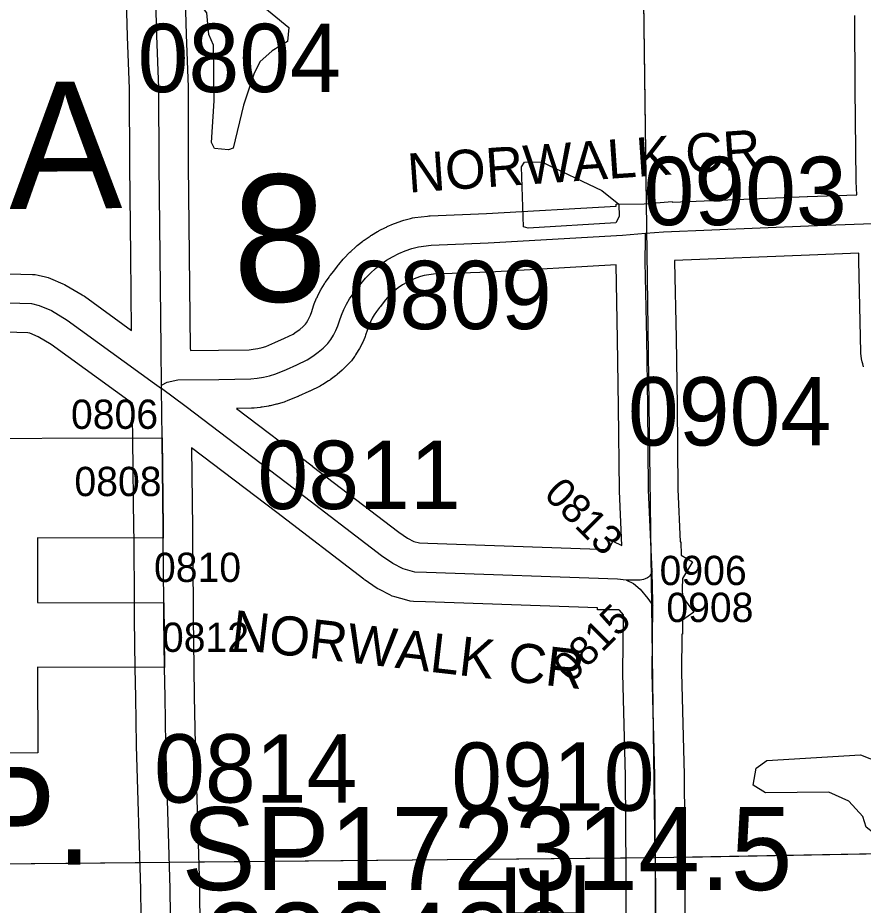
# Model space of a CAD drawing. Extents: x 23.6 to 68.7, y -63 to -29.
# Drawn here: x 46.003 to 46.869, y -47.606 to -46.697 of the extents above; entities that cross this region are included whole.
import ezdxf

# ---------------------------------------------------------------- set-up
doc = ezdxf.new("R2010")
doc.units = 0
for name, color, linetype in [('tdCoCorpBndry', 7, 'Continuous'), ('tdCoCorpPopTxt', 7, 'Continuous'), ('tdCoCorpTxt', 7, 'Continuous'), ('tdCoHydroRiver', 7, 'Continuous'), ('tdCoSecRdNmbr', 7, 'Continuous'), ('tdCoSecRdTxt', 7, 'Continuous'), ('tdCoSecRteBand', 7, 'Continuous'), ('tdCoSecRteCL', 7, 'Continuous'), ('tdCoSectLine', 7, 'Continuous'), ('tdCoSectLinePart', 7, 'Continuous'), ('tdCoSectNmbr', 7, 'Continuous'), ('tdCoStrucSecCoName', 7, 'Continuous'), ('tdCoStrucSecFHWANum', 7, 'Continuous'), ('tdCoSurfGravel', 7, 'Continuous')]:
    doc.layers.add(name, color=color, linetype=linetype)

msp = doc.modelspace()

# ---------------------------------------------------------------- linework, layer by layer
at = {"layer": 'tdCoCorpBndry'}
msp.add_lwpolyline([(45.9041, -47.12823), (46.15075, -47.12738), (46.15186, -47.22042), (46.15192, -47.23031), (46.02292, -47.22989), (46.02298, -47.29617), (46.15237, -47.2966), (46.15325, -47.36289), (46.02304, -47.36246), (46.02355, -47.45028), (45.90584, -47.45112)], dxfattribs=at)
at = {"layer": 'tdCoHydroRiver'}
for points in [[(46.21866, -46.83257), (46.20444, -46.83114), (46.20121, -46.82486), (46.2039, -46.78222), (46.20328, -46.72539), (46.19843, -46.71439), (46.19661, -46.69232), (46.1918, -46.68606), (46.1901, -46.67502), (46.18204, -46.65932), (46.18015, -46.63093), (46.22891, -46.61461), (46.23841, -46.61766), (46.2432, -46.62235), (46.25017, -46.68225), (46.28043, -46.70718), (46.27901, -46.7214), (46.26332, -46.73105), (46.25082, -46.74223), (46.24465, -46.75493), (46.23394, -46.78662), (46.22338, -46.83093), (46.21866, -46.83257)], [(46.52578, -46.91286), (46.52102, -46.91134), (46.51877, -46.8498), (46.52188, -46.84502), (46.53924, -46.84483), (46.60112, -46.87415), (46.61863, -46.88816), (46.61878, -46.90079), (46.61569, -46.90714), (46.52578, -46.91286)], [(46.89719, -47.53232), (46.87982, -47.53251), (46.87186, -47.52629), (46.86859, -47.51527), (46.85421, -47.49964), (46.83359, -47.49039), (46.76887, -47.49111), (46.75616, -47.48335), (46.75913, -47.46596), (46.77009, -47.45795), (46.86632, -47.45215), (46.88534, -47.45983), (46.89176, -47.46924), (46.90022, -47.52124), (46.89719, -47.53232)]]:
    msp.add_lwpolyline(points, dxfattribs=at)
at = {"layer": 'tdCoSecRteBand'}
for points in [[(45.95845, -46.95837), (46.01788, -46.96009), (46.02078, -46.96018), (46.02361, -46.96082), (46.03126, -46.96254), (46.03398, -46.96316), (46.03653, -46.96426), (46.04911, -46.96969), (46.05086, -46.97044), (46.05249, -46.9714), (46.06877, -46.98102), (46.06997, -46.98173), (46.07111, -46.98256), (46.1194, -47.01755), (46.11857, -46.94106), (46.11755, -46.84858), (46.11754, -46.84846), (46.11754, -46.84833), (46.11734, -46.76995), (46.1153, -46.71643), (46.1153, -46.71626), (46.11529, -46.7161), (46.11365, -46.65527)], [(46.17364, -46.65396), (46.17527, -46.71431), (46.17732, -46.7682), (46.17734, -46.76873), (46.17734, -46.76926), (46.17754, -46.84805), (46.17857, -46.9404), (46.17857, -46.9404), (46.17857, -46.9404), (46.1796, -47.03552), (46.17963, -47.03802)], [(46.17963, -47.03802), (46.20849, -47.03768), (46.23999, -47.03721), (46.24415, -47.03677), (46.24867, -47.03601), (46.25312, -47.03497), (46.25693, -47.03382), (46.26605, -47.03), (46.27609, -47.02546), (46.28486, -47.02121), (46.28818, -47.0191), (46.29183, -47.01641), (46.29528, -47.01346), (46.29756, -47.0112), (46.29856, -47.00984), (46.30012, -47.00733), (46.30148, -47.00471), (46.30265, -47.00199), (46.30393, -46.99825), (46.30587, -46.99242), (46.30621, -46.9914), (46.30662, -46.9904), (46.30902, -46.98461), (46.30944, -46.98361), (46.30992, -46.98265), (46.31273, -46.97705), (46.31322, -46.97608), (46.31377, -46.97516), (46.31697, -46.96977), (46.31753, -46.96885), (46.31814, -46.96796), (46.32173, -46.96282), (46.32235, -46.96194), (46.32303, -46.9611), (46.32654, -46.95676), (46.33036, -46.95159), (46.33095, -46.95078), (46.33159, -46.95003), (46.33618, -46.9446), (46.33683, -46.94384), (46.33752, -46.94312), (46.34246, -46.93801), (46.34315, -46.9373), (46.34389, -46.93663), (46.34915, -46.93186), (46.34989, -46.93119), (46.35067, -46.93057), (46.35624, -46.92616), (46.35702, -46.92554), (46.35784, -46.92498), (46.36369, -46.92094), (46.36451, -46.92038), (46.36537, -46.91987), (46.37147, -46.91623), (46.37233, -46.91572), (46.37321, -46.91527), (46.37955, -46.91205), (46.38044, -46.9116), (46.38135, -46.91121), (46.38788, -46.90841), (46.3888, -46.90802), (46.38974, -46.90769), (46.39644, -46.90533), (46.39738, -46.905), (46.39834, -46.90473), (46.40518, -46.90282), (46.40732, -46.90222), (46.40952, -46.90195), (46.42268, -46.9003), (46.42394, -46.90015), (46.42521, -46.9001), (46.48315, -46.8978), (46.61579, -46.89021), (46.61577, -46.88814), (46.64464, -46.88795), (46.67341, -46.88559), (46.67345, -46.88603), (46.81168, -46.88037), (46.81173, -46.88037), (46.81178, -46.88036), (46.8623, -46.87847), (46.86184, -46.86501), (46.86183, -46.86465), (46.86183, -46.86429), (46.86087, -46.76986), (46.86087, -46.76981), (46.86087, -46.76976), (46.86038, -46.69495)], [(46.86935, -47.05485), (46.86851, -47.05183), (46.86788, -47.04959), (46.86704, -47.04657), (46.86684, -47.04345), (46.86668, -47.04112), (46.86664, -47.04047), (46.86663, -47.03982), (46.86463, -46.94636), (46.86436, -46.93843), (46.81409, -46.94032), (46.6757, -46.94599), (46.67568, -46.94708), (46.67731, -47.02514), (46.67732, -47.02524), (46.67732, -47.02534), (46.6783, -47.09488), (46.6783, -47.09495), (46.67831, -47.09502), (46.67912, -47.18), (46.68149, -47.23415), (46.68224, -47.23414), (46.68249, -47.24759), (46.694, -47.25456), (46.68369, -47.27158), (46.68359, -47.28221), (46.68394, -47.29023), (46.69528, -47.30613), (46.68372, -47.31436), (46.68398, -47.32855), (46.68316, -47.32856), (46.68279, -47.36783), (46.68541, -47.4727), (46.68541, -47.47295), (46.68541, -47.47319), (46.68624, -47.57085), (46.68624, -47.57092), (46.68624, -47.571), (46.68656, -47.66733)], [(46.60829, -47.24188), (46.6124, -47.23337), (46.62159, -47.23781), (46.61916, -47.18211), (46.61914, -47.1816), (46.61913, -47.18109), (46.61831, -47.09567), (46.61732, -47.02629), (46.61574, -46.95031), (46.48631, -46.95772), (46.48605, -46.95774), (46.48578, -46.95775), (46.42885, -46.96), (46.41917, -46.96121), (46.41542, -46.96226), (46.41059, -46.96395), (46.40588, -46.96597), (46.40132, -46.96829), (46.39693, -46.97091), (46.39271, -46.97381), (46.3887, -46.97699), (46.38491, -46.98043), (46.38135, -46.98411), (46.37804, -46.98802), (46.37441, -46.99293), (46.37401, -46.99348), (46.37358, -46.99401), (46.37032, -46.99804), (46.36797, -47.0014), (46.36587, -47.00493), (46.36403, -47.00859), (46.36246, -47.01239), (46.36082, -47.0173), (46.36078, -47.01743), (46.36074, -47.01755), (46.35905, -47.02249), (46.35869, -47.02356), (46.35824, -47.0246), (46.35618, -47.0294), (46.35573, -47.03044), (46.35521, -47.03144), (46.3528, -47.03607), (46.35227, -47.03708), (46.35167, -47.03804), (46.34892, -47.04248), (46.34832, -47.04344), (46.34765, -47.04435), (46.34457, -47.04857), (46.34315, -47.0505), (46.34144, -47.05219), (46.33668, -47.05689), (46.33592, -47.05765), (46.3351, -47.05835), (46.33002, -47.0627), (46.3292, -47.0634), (46.32833, -47.06404), (46.32295, -47.06801), (46.32208, -47.06865), (46.32117, -47.06923), (46.31552, -47.07281), (46.3141, -47.07371), (46.31258, -47.07444), (46.30192, -47.07962), (46.30155, -47.0798), (46.30117, -47.07997), (46.29037, -47.08485), (46.28999, -47.08502), (46.28961, -47.08518), (46.27868, -47.08976), (46.27725, -47.09036), (46.27576, -47.09081), (46.26957, -47.09268), (46.26866, -47.09295), (46.26774, -47.09317), (46.26144, -47.09465), (46.26051, -47.09486), (46.25958, -47.09502), (46.2532, -47.0961), (46.25226, -47.09625), (46.25132, -47.09635), (46.24488, -47.09702), (46.24356, -47.09716), (46.24222, -47.09718), (46.22693, -47.09741), (46.30445, -47.15633), (46.30449, -47.15636), (46.30453, -47.15639), (46.39309, -47.22415), (46.40219, -47.23028), (46.40858, -47.23355), (46.4144, -47.23522), (46.42281, -47.23556), (46.60829, -47.24188)], [(46.12986, -47.67186), (46.12908, -47.58965), (46.12443, -47.44292), (46.12443, -47.44266), (46.12442, -47.4424), (46.12371, -47.39329), (46.12325, -47.36355), (46.12325, -47.36355), (46.12325, -47.36335), (46.12248, -47.31316), (46.12248, -47.31302), (46.12248, -47.31289), (46.12237, -47.29702), (46.12237, -47.2968), (46.12193, -47.23074), (46.12193, -47.23073), (46.12193, -47.23073), (46.12193, -47.2305), (46.12186, -47.22069), (46.12083, -47.12934), (46.12082, -47.12803), (46.12082, -47.12803), (46.12082, -47.12802), (46.12081, -47.12777), (46.12054, -47.10743), (46.12034, -47.09232), (46.03704, -47.03197), (46.0236, -47.02403), (46.01533, -47.02046), (46.01323, -47.01998), (45.95724, -47.01836)], [(46.62657, -47.66771), (46.62624, -47.57128), (46.62542, -47.47395), (46.62279, -47.36881), (46.62278, -47.3683), (46.62279, -47.36778), (46.62334, -47.30884), (46.61926, -47.30399), (46.61868, -47.30352), (46.5967, -47.30376), (46.59668, -47.30152), (46.42067, -47.29552), (46.42057, -47.29552), (46.42046, -47.29552), (46.40838, -47.29502), (46.4048, -47.29488), (46.40136, -47.29389), (46.38928, -47.29044), (46.38646, -47.28964), (46.38386, -47.2883), (46.37325, -47.28288), (46.37165, -47.28206), (46.37015, -47.28105), (46.35881, -47.2734), (46.35806, -47.2729), (46.35734, -47.27235), (46.26811, -47.20407), (46.18093, -47.13782), (46.18186, -47.22009), (46.18186, -47.22015), (46.18186, -47.22022), (46.18192, -47.2301), (46.18192, -47.23011), (46.18192, -47.23011), (46.18193, -47.23034), (46.18237, -47.29639), (46.18237, -47.29661), (46.18247, -47.31236), (46.18324, -47.36243), (46.18324, -47.36243), (46.18325, -47.36263), (46.18371, -47.39238), (46.18371, -47.39239), (46.18371, -47.39241), (46.18441, -47.44128), (46.18906, -47.58809), (46.18907, -47.58842), (46.18908, -47.58875), (46.18986, -47.67138)]]:
    msp.add_lwpolyline(points, dxfattribs=at)
at = {"layer": 'tdCoSecRteCL'}
msp.add_line((46.15014, -47.07703), (46.1501, -47.07343), dxfattribs=at)
for points in [[(46.1501, -47.07343), (46.1496, -47.03588), (46.14857, -46.94073), (46.14754, -46.84825), (46.14734, -46.76934), (46.14528, -46.71529), (46.14364, -46.65446), (46.14343, -46.62158), (46.14241, -46.57596), (46.1422, -46.54349), (46.14241, -46.51389), (46.14117, -46.44752), (46.14056, -46.42306), (46.13973, -46.3575), (46.1385, -46.3127), (46.13706, -46.23975), (46.13624, -46.15303), (46.1348, -46.05726), (46.13275, -45.98143), (46.1309, -45.92882), (46.12966, -45.8608), (46.12987, -45.78455)], [(46.64597, -46.91794), (46.66445, -46.91643), (46.81291, -46.91034), (46.87851, -46.90788), (46.88804, -46.90508), (46.89318, -46.90358)], [(46.1501, -47.07343), (46.15579, -47.07064), (46.1668, -47.06817), (46.20889, -47.06768), (46.24177, -47.06719), (46.24821, -47.06651), (46.25459, -47.06544), (46.26089, -47.06396), (46.26709, -47.06209), (46.27802, -47.05751), (46.28882, -47.05263), (46.29948, -47.04746), (46.30513, -47.04388), (46.31051, -47.0399), (46.3156, -47.03555), (46.32036, -47.03085), (46.32344, -47.02664), (46.3262, -47.0222), (46.32861, -47.01757), (46.33067, -47.01278), (46.33236, -47.00784), (46.33433, -47.00189), (46.33673, -46.9961), (46.33954, -46.99051), (46.34275, -46.98512), (46.34633, -46.97999), (46.35028, -46.97512), (46.3545, -46.9694), (46.35909, -46.96397), (46.36403, -46.95886), (46.3693, -46.95409), (46.37487, -46.94968), (46.38072, -46.94564), (46.38683, -46.94201), (46.39316, -46.93878), (46.39969, -46.93598), (46.4064, -46.93363), (46.41324, -46.93172), (46.4264, -46.93007), (46.4846, -46.92777), (46.62237, -46.91988), (46.64597, -46.91794)], [(46.6528, -47.26469), (46.64913, -47.1808), (46.64831, -47.09531), (46.64732, -47.02577), (46.64568, -46.94718), (46.64601, -46.92384), (46.64597, -46.91794)], [(45.95757, -46.98835), (46.01701, -46.99008), (46.02465, -46.99181), (46.03723, -46.99723), (46.0535, -47.00685), (46.14302, -47.07171), (46.15014, -47.07703)], [(46.16124, -47.811), (46.16017, -47.74663), (46.15986, -47.67166), (46.15908, -47.58904), (46.15442, -47.44197), (46.15371, -47.39284), (46.15325, -47.36309), (46.15325, -47.36289), (46.15248, -47.31269), (46.15237, -47.29681), (46.15237, -47.2966), (46.15193, -47.23054), (46.15193, -47.23031), (46.15186, -47.22042), (46.15083, -47.12897), (46.15081, -47.12763), (46.15081, -47.12737), (46.15014, -47.07703)], [(46.62637, -47.27343), (46.62616, -47.2734), (46.61725, -47.2722), (46.42169, -47.26554), (46.4096, -47.26505), (46.39752, -47.26159), (46.38692, -47.25617), (46.37557, -47.24852), (46.2863, -47.18021), (46.17533, -47.09588), (46.15014, -47.07703)], [(46.6528, -47.26469), (46.64988, -47.26952), (46.6481, -47.27091), (46.64556, -47.27205), (46.64391, -47.27269), (46.64048, -47.2732), (46.63616, -47.27332), (46.62637, -47.27343)], [(46.65343, -47.2991), (46.65337, -47.2955), (46.6528, -47.26469)], [(46.62637, -47.27343), (46.63352, -47.27688), (46.64043, -47.28256), (46.64832, -47.29193), (46.65343, -47.2991)], [(46.65846, -47.80391), (46.65821, -47.77595), (46.65657, -47.66761), (46.65624, -47.5711), (46.65541, -47.47345), (46.65278, -47.36806), (46.65343, -47.2991)]]:
    msp.add_lwpolyline(points, dxfattribs=at)
at = {"layer": 'tdCoSectLine'}
for points in [[(46.65578, -47.55744), (46.64259, -46.55037)], [(46.65578, -47.55744), (47.64586, -47.53943)], [(45.66118, -47.56702), (46.65578, -47.55744)], [(46.65578, -47.55744), (46.66417, -48.5626)]]:
    msp.add_lwpolyline(points, dxfattribs=at)
at = {"layer": 'tdCoSectLinePart'}
for points in [[(46.64701, -46.88775), (46.64259, -46.55037)], [(46.68583, -47.55689), (47.6158, -47.53997)], [(46.18788, -47.56194), (46.62559, -47.55773)], [(45.66118, -47.56702), (46.12789, -47.56252)]]:
    msp.add_lwpolyline(points, dxfattribs=at)
at = {"layer": 'tdCoSurfGravel'}
for p, q in [((46.15081, -47.12763), (46.15081, -47.12737)), ((46.15193, -47.23054), (46.15193, -47.23031)), ((46.15237, -47.2966), (46.15193, -47.23054)), ((46.15237, -47.29681), (46.15237, -47.2966)), ((46.15325, -47.36309), (46.15325, -47.36289))]:
    msp.add_line(p, q, dxfattribs=at)
for points in [[(46.15081, -47.12737), (46.15014, -47.07703), (46.1501, -47.07343), (46.1496, -47.03588), (46.14857, -46.94073), (46.14754, -46.84825), (46.14734, -46.76934), (46.14528, -46.71529), (46.14364, -46.65446), (46.14343, -46.62158), (46.14241, -46.57596), (46.1422, -46.54349), (46.14241, -46.51389), (46.14117, -46.44752), (46.14056, -46.42306), (46.13973, -46.3575), (46.1385, -46.3127), (46.13706, -46.23975), (46.13624, -46.15303), (46.1348, -46.05726), (46.13275, -45.98143), (46.1309, -45.92882), (46.12966, -45.8608), (46.12987, -45.78455)], [(46.1501, -47.07343), (46.15579, -47.07064), (46.1668, -47.06817), (46.20889, -47.06768), (46.24177, -47.06719), (46.24821, -47.06651), (46.25459, -47.06544), (46.26089, -47.06396), (46.26709, -47.06209), (46.27802, -47.05751), (46.28882, -47.05263), (46.29948, -47.04746), (46.30513, -47.04388), (46.31051, -47.0399), (46.3156, -47.03555), (46.32036, -47.03085), (46.32344, -47.02664), (46.3262, -47.0222), (46.32861, -47.01757), (46.33067, -47.01278), (46.33236, -47.00784), (46.33433, -47.00189), (46.33673, -46.9961), (46.33954, -46.99051), (46.34275, -46.98512), (46.34633, -46.97999), (46.35028, -46.97512), (46.3545, -46.9694), (46.35909, -46.96397), (46.36403, -46.95886), (46.3693, -46.95409), (46.37487, -46.94968), (46.38072, -46.94564), (46.38683, -46.94201), (46.39316, -46.93878), (46.39969, -46.93598), (46.4064, -46.93363), (46.41324, -46.93172), (46.4264, -46.93007), (46.4846, -46.92777), (46.62237, -46.91988), (46.64597, -46.91794), (46.66445, -46.91643), (46.81291, -46.91034), (46.87851, -46.90788)], [(46.65337, -47.2955), (46.6528, -47.26469), (46.64913, -47.1808), (46.64831, -47.09531), (46.64732, -47.02577), (46.64568, -46.94718), (46.64601, -46.92384), (46.64597, -46.91794)], [(45.95757, -46.98835), (46.01701, -46.99008), (46.02465, -46.99181), (46.03723, -46.99723), (46.0535, -47.00685), (46.14302, -47.07171), (46.15014, -47.07703)], [(46.62616, -47.2734), (46.61725, -47.2722), (46.42169, -47.26554), (46.4096, -47.26505), (46.39752, -47.26159), (46.38692, -47.25617), (46.37557, -47.24852), (46.2863, -47.18021), (46.17533, -47.09588), (46.15014, -47.07703)], [(46.15193, -47.23031), (46.15186, -47.22042), (46.15083, -47.12897), (46.15081, -47.12763)], [(46.6528, -47.26469), (46.64988, -47.26952), (46.6481, -47.27091), (46.64556, -47.27205), (46.64391, -47.27269), (46.64048, -47.2732), (46.63616, -47.27332), (46.62637, -47.27343), (46.62616, -47.2734)], [(46.62637, -47.27343), (46.63352, -47.27688), (46.64043, -47.28256), (46.64832, -47.29193), (46.65343, -47.2991)], [(46.65624, -47.5711), (46.65541, -47.47345), (46.65278, -47.36806), (46.65343, -47.2991), (46.65337, -47.2955)], [(46.15325, -47.36289), (46.15248, -47.31269), (46.15237, -47.29681)], [(46.16337, -48.0976), (46.16314, -48.04135), (46.16273, -47.99983), (46.16236, -47.96201), (46.16173, -47.89688), (46.16124, -47.811), (46.16017, -47.74663), (46.15986, -47.67166), (46.15908, -47.58904), (46.15442, -47.44197), (46.15371, -47.39284), (46.15325, -47.36309)], [(46.66359, -48.31163), (46.66314, -48.28297), (46.66232, -48.22872), (46.66183, -48.12827), (46.661, -48.03653), (46.65985, -47.94578), (46.65887, -47.85026), (46.65846, -47.80391), (46.65821, -47.77595), (46.65657, -47.66761), (46.65624, -47.5711)]]:
    msp.add_lwpolyline(points, dxfattribs=at)

# ---------------------------------------------------------------- texts
at = {"layer": 'tdCoCorpPopTxt'}
msp.add_text('POP.', height=0.1, dxfattribs=at).set_placement((45.7597, -47.56461))
at = {"layer": 'tdCoCorpTxt'}
msp.add_text('OSKALOOSA', height=0.13, rotation=0.46989, dxfattribs=at).set_placement((45.02808, -46.90106))
at = {"layer": 'tdCoSecRdNmbr'}
for s, height, rotation, p in [('0804', 0.07, 0.03578, (46.12563, -46.77348)), ('0903', 0.07, 0.03631, (46.6439, -46.90971)), ('0809', 0.07, 0.03609, (46.34171, -47.01624)), ('0904', 0.07, 0.03631, (46.62793, -47.13538)), ('0806', 0.03, 0.03628, (46.05736, -47.11838)), ('0811', 0.07, 0.03601, (46.2484, -47.20049)), ('0808', 0.03, 0.03628, (46.06089, -47.18723)), ('0813', 0.03, 315.03544, (46.54065, -47.1867)), ('0810', 0.03, 0.03628, (46.1424, -47.27518)), ('0906', 0.03, 0.03628, (46.66037, -47.27836)), ('0908', 0.03, 0.03628, (46.6673, -47.31619)), ('0815', 0.03, 45.03483, (46.56992, -47.37951)), ('0812', 0.03, 0.03628, (46.15054, -47.34679)), ('0814', 0.07, 0.03594, (46.14246, -47.50115)), ('0910', 0.07, 0.03617, (46.44696, -47.50958))]:
    msp.add_text(s, height=height, rotation=rotation, dxfattribs=at).set_placement(p)
at = {"layer": 'tdCoSecRdTxt'}
for s, height, rotation, p in [('NORWALK CR', 0.04, 3.95678, (46.40341, -46.87642)), ('NORWALK CR', 0.04, 353.41594, (46.22026, -47.34349)), ('OSBURN AVE', 0.08, 90, (46.5833, -48.26222))]:
    msp.add_text(s, height=height, rotation=rotation, dxfattribs=at).set_placement(p)
at = {"layer": 'tdCoSectNmbr'}
msp.add_text('8', height=0.13, rotation=1.03592, dxfattribs=at).set_placement((46.22386, -46.98882))
at = {"layer": 'tdCoStrucSecCoName'}
msp.add_text('SP172314.5', height=0.085, dxfattribs=at).set_placement((46.17074, -47.59072))
at = {"layer": 'tdCoStrucSecFHWANum'}
msp.add_text('236400', height=0.085, dxfattribs=at).set_placement((46.19416, -47.68873))

doc.saveas('drawing.dxf')
